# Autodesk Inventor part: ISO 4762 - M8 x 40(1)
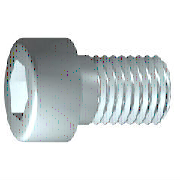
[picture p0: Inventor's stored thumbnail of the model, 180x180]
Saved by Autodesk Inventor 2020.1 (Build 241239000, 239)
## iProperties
Created: 2019-01
Part Number: ISO 4762 - M8 x 40(1)
Material: Edelstahl, 440C
Description: Innensechskantschraube
Document SubType Name: Modeling
Standard: ISO 4762
Designer: lutzd
Standard Revision: Fourth edition 2004-03-01
Standards Organization: ISO
Language: de-DE
Size Designation: M8 x 40
Categories: <MemberInstance><Categories><Category DisplayName="Verbindungselemente" InternalName="e4da775c-781d-43d5-af7c-5136215cf5a6" Mnemonic="FSTN"><Category DisplayNam
Mass: 22.5603 g
Surface Area: 16.6168 cm^2
Volume: 2.91101 cm^3
Density: 7.75 g/cm^3
Appearance: Halbpoliert
IsCustomPart: 0
Author: lutzd
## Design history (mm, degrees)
workplane "Work Plane1"
fillet "Fillet2" dims "d30" = 0.1 (= R)
sketch "Skizze1"
  geometry: L1 (-2, 0)-(40, 0); L2 (40, 0)-(40, 4); L3 (40, 4)-(12, 4); L4 (12, 4)-(11.233, 4); L5 (11.233, 4)-(0, 4); L6 (0, 4)-(0, 6.5); L7 (0, 6.5)-(-8, 6.5); L8 (-8, 6.5)-(-8, 3.464); L9 (-8, 3.464)-(-4, 3.464); L10 (-4, 3.464)-(-2, 0); L11 (-17.6, 0)-(49.6, 0) reference; L12 (0, -1.3)-(0, 7.8) reference; L13 (12, 4)-(0, 4)
  constraints: 22 end point, 6 parallel, 2 collinear, 2 perpendicular, 1 horizontal, 1 point on line
  dimensions: "d1" = 28 distance from line of L3.end L2 (= GEL); "d2" = 0.76691 distance of L4.end L3.end (computed from GAL); "d3" = 8 distance between parallel lines of L8 L6 (= KOH); "d4" = 4 distance of L8.end L9.end (= INTI); "d5" = 60 deg angle of L10 L1; "d6" = 8 diameter of L3 L1 (= GD); "d7" = 8 diameter of L5 L1 (= BDM); "d8" = 6.9282 diameter of L9 L1 (= 1.1547 x SW); "d9" = 13 diameter of L7 L1 (= KOD); "d26" = 40 distance between parallel lines of L12 L2 (= NLG)
revolve "Körper" sketch "Skizze1" stored, may be unused: angle "d10" = 90 deg
sketch "Skizze2"
  geometry: L1 (0, -9.1)-(0, 9.1) reference; L2 (-9.1, 0)-(9.1, 0) reference; L3 (3.464, 0)-(1.732, -3); L4 (1.732, -3)-(-1.732, -3); L5 (-1.732, -3)-(-3.464, 0); L6 (-3.464, 0)-(-1.732, 3); L7 (-1.732, 3)-(1.732, 3); L8 (1.732, 3)-(3.464, 0); 2 further points
  constraints: 12 end point, 1 coincident, 1 horizontal alignment, 1 point on line, 12 other
extrude "Loch" join sketch "Skizze2" stored distance "d11" = 10; taper "d12" = 0 deg
body "Solid1"
fillet "Rundung1" dims "d17" = 0.8 (= RR)
feature "Gewinde" dims "d13" = 28 (= GEL), "d14" = 0
chamfer "Fase1" distance "d15" = 0.76681 (= -0.5 x SPD + 0.5 x GD); stored, may be unused: second distance "d16" = 0.76681 (= GUL), angle "d27" = 45 deg
other parameters: "GD" = 8 [user parameter; used in 2 equation terms], "NLG" = 40 [user parameter; used in 1 equation term], "GEL" = 28 [user parameter; used in 2 equation terms], "KOD" = 13 [user parameter; used in 1 equation term], "KOH" = 8 [user parameter; used in 1 equation term], "INTI" = 4 [user parameter; used in 1 equation term], "GAL" = 0.76681 (= 0.61345 x PTC) [user parameter; used in 1 equation term], "GUL" = 0.76681 (= 0.61345 x PTC) [user parameter; used in 1 equation term], "BDM" = 8 (= NND) [user parameter; used in 1 equation term], "SW" = 6 [user parameter; used in 2 equation terms], "RR" = 0.8 [user parameter; used in 1 equation term], "SPD" = 6.46637 (= NND - 1.2269 x PTC) [user parameter; used in 1 equation term], "d19" = 0, "d28" = 0, "d29" = 0, "R" = 0.1 [user parameter; used in 1 equation term], "TOA" = 30 deg [user parameter], "GD1" = 6.46637 (= THREADDIA - 1.2269 x PTC) [user parameter], "THREADDIA" = 8 [user parameter; used in 1 equation term], "FAWI" = 45 deg [user parameter], "TPU" = 8 (computed from PTC) [user parameter], "PTC" = 1.25 [user parameter; used in 5 equation terms], "NND" = 8 [user parameter; used in 2 equation terms], "E0" = 6.93 (= 1.155 x SW) [user parameter]
